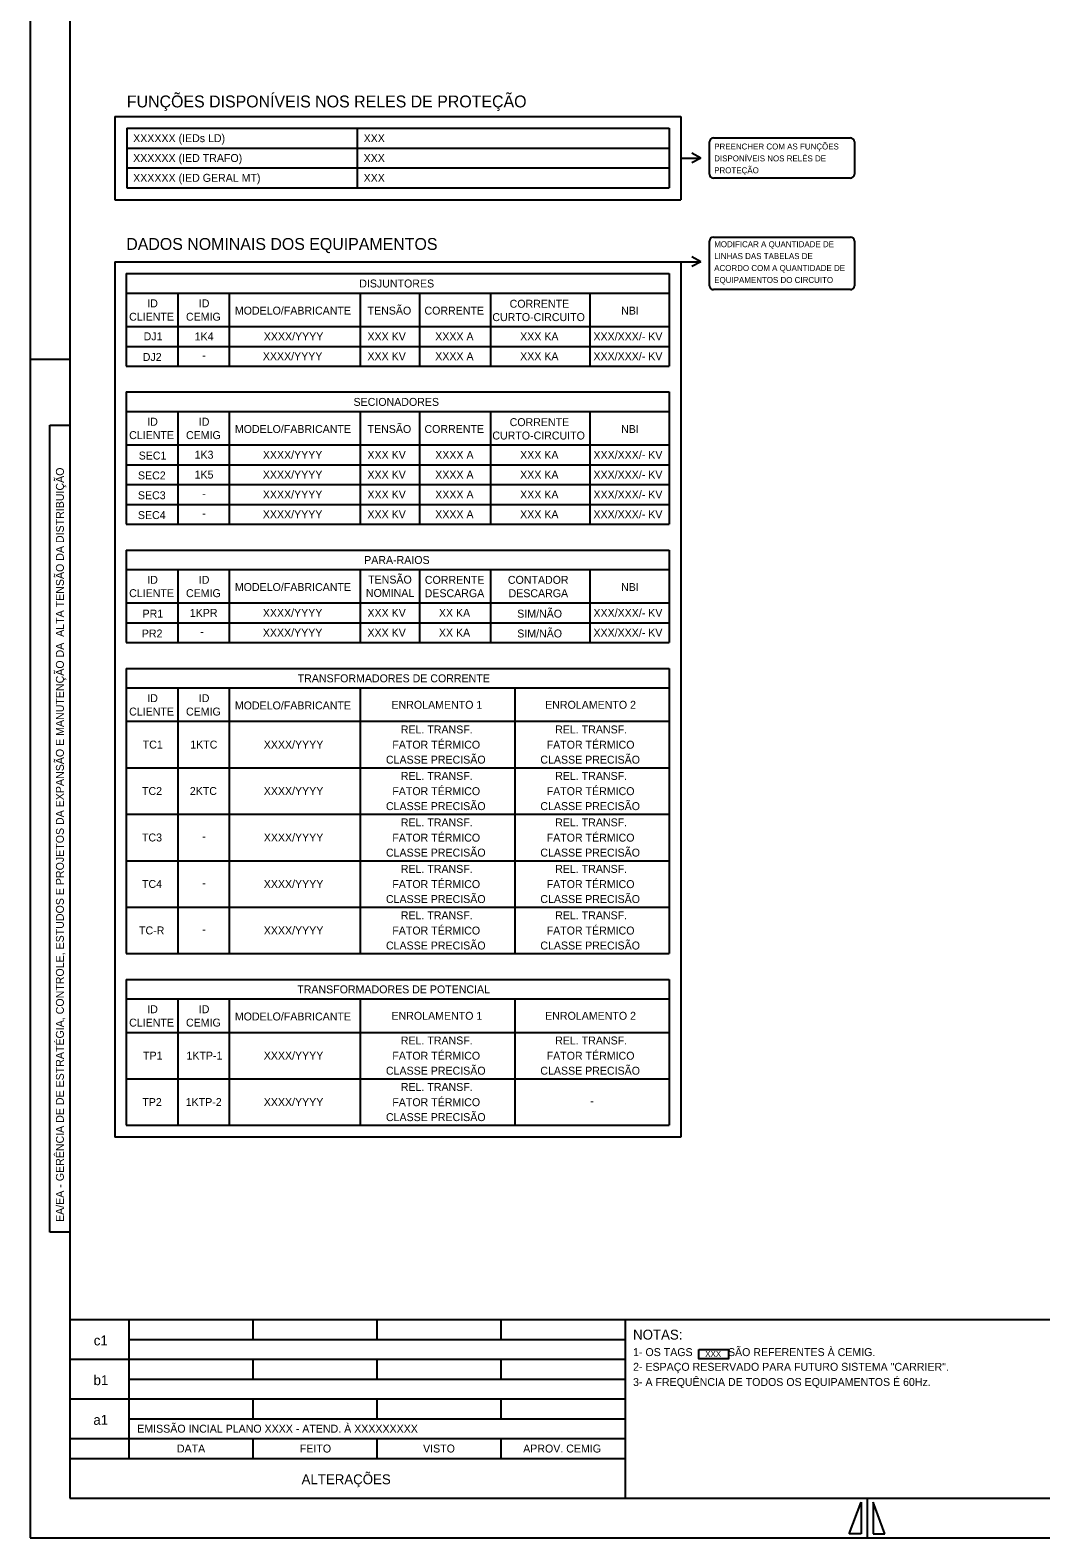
# Model space of a CAD drawing. Extents: x 563 to 1404, y 358 to 952.
# Drawn here: x 562.6 to 817.4, y 358 to 737.8 of the extents above; entities that cross this region are included whole.
import ezdxf

# ---------------------------------------------------------------- set-up
doc = ezdxf.new("R2010")
doc.units = 0
doc.layers.add('New Level (0)', color=7, linetype='Continuous')

# ---------------------------------------------------------------- blocks, each defined once
blk = doc.blocks.new('POINT_DISPLAY')
blk.add_line((0, 0), (0, 0))

msp = doc.modelspace()

# ---------------------------------------------------------------- linework, layer by layer
at = {"layer": 'New Level (0)'}
for p, q in [((562.58, 951.96), (562.58, 357.96)), ((562.58, 951.96), (562.58, 357.96)), ((572.58, 941.96), (572.58, 367.96)), ((572.58, 941.96), (572.58, 367.96)), ((583.96, 716.12), (583.96, 695.12)), ((583.96, 716.12), (726.65, 716.12)), ((726.65, 716.12), (726.65, 695.12)), ((586.96, 713.12), (723.65, 713.12)), ((586.96, 713.12), (586.96, 698.12)), ((586.96, 713.12), (586.96, 713.12)), ((586.96, 713.12), (586.96, 713.12)), ((645.01, 713.12), (645.01, 698.12)), ((723.65, 713.12), (723.65, 698.12)), ((734.84, 710.67), (742.19, 710.67)), ((742.19, 710.67), (769.38, 710.67)), ((586.96, 708.12), (723.65, 708.12)), ((731.68, 705.62), (729.38, 706.83)), ((733.84, 701.56), (733.84, 709.67)), ((770.38, 709.67), (770.38, 701.56)), ((586.96, 703.12), (723.65, 703.12)), ((726.65, 705.62), (731.68, 705.62)), ((731.68, 705.62), (729.38, 704.41)), ((769.38, 700.56), (734.84, 700.56)), ((586.96, 698.12), (723.65, 698.12)), ((583.96, 695.12), (726.65, 695.12)), ((733.84, 673.45), (733.84, 684.7)), ((734.84, 685.7), (742.19, 685.7)), ((742.19, 685.7), (769.38, 685.7)), ((770.38, 684.7), (770.38, 673.45)), ((731.68, 679.5), (729.38, 680.71)), ((583.96, 679.5), (726.65, 679.5)), ((583.96, 679.5), (583.96, 458.91)), ((586.81, 676.5), (586.81, 653.17)), ((586.81, 676.5), (723.65, 676.5)), ((723.65, 676.5), (723.65, 653.17)), ((726.65, 679.5), (731.68, 679.5)), ((726.65, 679.5), (726.65, 458.91)), ((731.68, 679.5), (729.38, 678.29)), ((769.38, 672.45), (734.84, 672.45)), ((723.65, 671.5), (586.81, 671.5)), ((599.81, 671.5), (599.81, 653.17)), ((612.81, 653.17), (612.81, 671.5)), ((645.81, 671.5), (645.81, 653.17)), ((660.72, 671.5), (660.72, 653.17)), ((678.66, 671.5), (678.66, 653.17)), ((703.66, 671.5), (703.66, 653.17)), ((586.81, 663.17), (723.65, 663.17)), ((586.81, 658.17), (723.65, 658.17)), ((562.58, 654.96), (572.58, 654.96)), ((586.81, 653.17), (723.65, 653.17)), ((586.81, 653.17), (586.81, 653.17)), ((586.81, 646.67), (586.81, 613.34)), ((586.81, 646.67), (723.65, 646.67)), ((723.65, 646.67), (723.65, 613.34)), ((567.58, 638.29), (572.58, 638.29)), ((567.58, 434.97), (567.58, 638.29)), ((723.65, 641.67), (586.81, 641.67)), ((599.81, 641.67), (599.81, 613.34)), ((612.81, 613.34), (612.81, 641.67)), ((645.81, 641.67), (645.81, 613.34)), ((660.72, 641.67), (660.72, 613.34)), ((678.66, 641.67), (678.66, 613.34)), ((703.66, 641.67), (703.66, 613.34)), ((586.81, 633.34), (723.65, 633.34)), ((586.81, 628.34), (723.65, 628.34)), ((586.81, 623.34), (723.65, 623.34)), ((586.81, 618.34), (723.65, 618.34)), ((586.81, 613.34), (723.65, 613.34)), ((586.81, 606.84), (586.81, 583.52)), ((586.81, 606.84), (723.65, 606.84)), ((723.65, 606.84), (723.65, 583.52)), ((723.65, 601.84), (586.81, 601.84)), ((599.81, 601.84), (599.81, 583.52)), ((612.81, 583.52), (612.81, 601.84)), ((645.81, 601.84), (645.81, 583.52)), ((660.72, 601.84), (660.72, 583.52)), ((678.66, 601.84), (678.66, 583.52)), ((703.66, 601.84), (703.66, 583.52)), ((586.81, 593.52), (723.65, 593.52)), ((629.06, 593.52), (723.65, 593.52)), ((586.81, 588.52), (723.65, 588.52)), ((586.81, 583.52), (723.65, 583.52)), ((586.81, 577.02), (586.81, 505.15)), ((586.81, 577.02), (723.65, 577.02)), ((723.65, 577.02), (723.65, 505.15)), ((723.65, 572.02), (586.81, 572.02)), ((599.81, 572.02), (599.81, 505.15)), ((612.81, 505.15), (612.81, 572.02)), ((645.81, 572.02), (645.81, 505.15)), ((684.73, 572.02), (684.73, 505.15)), ((586.81, 563.69), (723.65, 563.69)), ((586.81, 551.98), (723.65, 551.98)), ((586.81, 540.27), (723.65, 540.27)), ((586.81, 528.57), (723.65, 528.57)), ((586.81, 516.86), (723.65, 516.86)), ((586.81, 505.15), (723.65, 505.15)), ((586.81, 498.65), (586.81, 461.91)), ((586.81, 498.65), (723.65, 498.65)), ((723.65, 498.65), (723.65, 461.91)), ((723.65, 493.65), (586.81, 493.65)), ((599.81, 493.65), (599.81, 461.91)), ((612.81, 461.91), (612.81, 493.65)), ((645.81, 493.65), (645.81, 461.91)), ((684.73, 493.65), (684.73, 461.91)), ((586.81, 485.32), (723.65, 485.32)), ((586.81, 473.61), (723.65, 473.61)), ((586.81, 461.91), (723.65, 461.91)), ((726.65, 458.91), (583.96, 458.91)), ((572.58, 434.97), (567.58, 434.97)), ((572.58, 412.96), (1393.58, 412.96)), ((587.58, 377.96), (587.58, 412.96)), ((618.83, 407.96), (618.83, 412.96)), ((650.08, 407.96), (650.08, 412.96)), ((681.33, 407.96), (681.33, 412.96)), ((712.58, 412.96), (712.58, 367.96)), ((587.58, 407.96), (712.58, 407.96)), ((572.58, 402.96), (712.58, 402.96)), ((618.83, 397.96), (618.83, 402.96)), ((650.08, 397.96), (650.08, 402.96)), ((681.33, 397.96), (681.33, 402.96)), ((587.58, 397.96), (712.58, 397.96)), ((572.58, 392.96), (712.58, 392.96)), ((618.83, 387.96), (618.83, 392.96)), ((650.08, 387.96), (650.08, 392.96)), ((681.33, 387.96), (681.33, 392.96)), ((587.58, 387.96), (712.58, 387.96)), ((572.58, 382.96), (712.58, 382.96)), ((618.83, 377.96), (618.83, 382.96)), ((650.08, 377.96), (650.08, 382.96)), ((681.33, 377.96), (681.33, 382.96)), ((572.58, 377.96), (712.58, 377.96)), ((572.58, 367.96), (1393.58, 367.96)), ((572.58, 367.96), (1393.58, 367.96)), ((769.08, 358.96), (772.08, 366.96)), ((772.08, 366.96), (772.08, 358.96)), ((773.58, 367.96), (773.58, 357.96)), ((775.08, 366.96), (775.08, 358.96)), ((778.08, 358.96), (775.08, 366.96)), ((562.58, 357.96), (1403.58, 357.96)), ((562.58, 357.96), (1403.58, 357.96)), ((772.08, 358.96), (769.08, 358.96)), ((775.08, 358.96), (778.08, 358.96))]:
    msp.add_line(p, q, dxfattribs=at)
msp.add_lwpolyline([(731.16, 405.44), (738.67, 405.44), (738.67, 403.1), (731.16, 403.1)], close=True, dxfattribs=at)
for centre, start, end in [((734.84, 709.67), 90, 180), ((769.38, 709.67), 0, 90), ((734.84, 701.56), 180, 270), ((769.38, 701.56), 270, 0), ((734.84, 684.7), 90, 180), ((769.38, 684.7), 0, 90), ((734.84, 673.45), 180, 270), ((769.38, 673.45), 270, 0)]:
    msp.add_arc(centre, 1, start, end, dxfattribs=at)

# ---------------------------------------------------------------- block references
for p in [(670.01, 713.12), (655.23, 663.17), (655.23, 563.69), (655.23, 485.32)]:
    msp.add_blockref('POINT_DISPLAY', p, dxfattribs=at)

# ---------------------------------------------------------------- texts
for s, height, p in [('FUNÇÕES DISPONÍVEIS NOS RELES DE PROTEÇÃO', 3, (586.96, 718.37)), ('XXXXXX (IEDs LD)', 2, (588.55, 709.62)), ('XXX', 2, (646.65, 709.62)), ('XXXXXX (IED TRAFO)', 2, (588.55, 704.62)), ('XXX', 2, (646.65, 704.62)), ('PREENCHER COM AS FUNÇÕES ', 1.5, (735.03, 707.77)), ('DISPONÍVEIS NOS RELÉS DE ', 1.5, (735.03, 704.77)), ('PROTEÇÃO', 1.5, (735.03, 701.77)), ('XXXXXX (IED GERAL MT)', 2, (588.55, 699.62)), ('XXX', 2, (646.65, 699.62)), ('DADOS NOMINAIS DOS EQUIPAMENTOS', 3, (586.81, 682.46)), ('MODIFICAR A QUANTIDADE DE ', 1.5, (735.03, 683.15)), ('LINHAS DAS TABELAS DE ', 1.5, (735.03, 680.15)), ('ACORDO COM A QUANTIDADE DE ', 1.5, (735.03, 677.15)), ('DISJUNTORES', 2, (645.55, 673)), ('EQUIPAMENTOS DO CIRCUITO', 1.5, (735.03, 674.15)), ('ID', 2, (592.1, 668)), ('ID', 2, (605.1, 668)), ('TENSÃO', 2, (647.65, 666.17)), ('CORRENTE', 2, (683.46, 667.9)), ('CLIENTE', 2, (587.54, 664.63)), ('CEMIG', 2, (601.87, 664.63)), ('MODELO/FABRICANTE', 2, (614.19, 666.17)), ('CORRENTE', 2, (661.99, 666.17)), ('CURTO-CIRCUITO', 2, (679.1, 664.53)), ('NBI', 2, (711.56, 666.17)), ('DJ1', 2, (591.19, 659.68)), ('1K4', 2, (604.05, 659.67)), ('XXXX/YYYY', 2, (621.48, 659.67)), ('XXX KV', 2, (647.62, 659.67)), ('XXXX A', 2, (664.7, 659.67)), ('XXX KA', 2, (686.11, 659.67)), ('XXX/XXX/- KV', 2, (704.59, 659.67)), ('DJ2', 2, (590.97, 654.49)), ('-', 2, (605.94, 654.95)), ('XXXX/YYYY', 2, (621.24, 654.67)), ('XXX KV', 2, (647.62, 654.67)), ('XXXX A', 2, (664.7, 654.67)), ('XXX KA', 2, (686.11, 654.67)), ('XXX/XXX/- KV', 2, (704.59, 654.67)), ('SECIONADORES', 2, (644.11, 643.17)), ('ID', 2, (592.1, 638.17)), ('ID', 2, (605.1, 638.17)), ('MODELO/FABRICANTE', 2, (614.19, 636.34)), ('TENSÃO', 2, (647.65, 636.34)), ('CORRENTE', 2, (661.99, 636.34)), ('CORRENTE', 2, (683.46, 638.07)), ('NBI', 2, (711.56, 636.34)), ('CLIENTE', 2, (587.54, 634.8)), ('CEMIG', 2, (601.87, 634.8)), ('CURTO-CIRCUITO', 2, (679.1, 634.7)), ('SEC1', 2, (589.94, 629.65)), ('1K3', 2, (604.04, 629.86)), ('XXXX/YYYY', 2, (621.24, 629.84)), ('XXX KV', 2, (647.62, 629.84)), ('XXXX A', 2, (664.7, 629.84)), ('XXX KA', 2, (686.11, 629.84)), ('XXX/XXX/- KV', 2, (704.59, 629.84)), ('1K5', 2, (604.04, 624.86)), ('XXXX/YYYY', 2, (621.24, 624.84)), ('XXX KV', 2, (647.62, 624.84)), ('XXXX A', 2, (664.7, 624.84)), ('XXX KA', 2, (686.11, 624.84)), ('XXX/XXX/- KV', 2, (704.59, 624.84)), ('SEC2', 2, (589.76, 624.65)), ('SEC3', 2, (589.75, 619.65)), ('-', 2, (605.94, 620.12)), ('XXXX/YYYY', 2, (621.24, 619.84)), ('XXX KV', 2, (647.62, 619.84)), ('XXXX A', 2, (664.7, 619.84)), ('XXX KA', 2, (686.11, 619.84)), ('XXX/XXX/- KV', 2, (704.59, 619.84)), ('SEC4', 2, (589.75, 614.65)), ('-', 2, (605.94, 615.12)), ('XXXX/YYYY', 2, (621.24, 614.84)), ('XXX KV', 2, (647.62, 614.84)), ('XXXX A', 2, (664.7, 614.84)), ('XXX KA', 2, (686.11, 614.84)), ('XXX/XXX/- KV', 2, (704.59, 614.84)), ('PARA-RAIOS', 2, (646.79, 603.34)), ('ID', 2, (592.1, 598.34)), ('ID', 2, (605.1, 598.34)), ('TENSÃO ', 2, (647.79, 598.4)), ('CORRENTE', 2, (662.09, 598.33)), ('CONTADOR', 2, (683.02, 598.33)), ('CLIENTE', 2, (587.54, 594.98)), ('CEMIG', 2, (601.87, 594.98)), ('MODELO/FABRICANTE', 2, (614.19, 596.52)), ('NOMINAL', 2, (647.23, 595.03)), ('DESCARGA', 2, (662.05, 594.96)), ('DESCARGA', 2, (683.19, 594.96)), ('NBI', 2, (711.56, 596.52)), ('PR1', 2, (590.92, 589.82)), ('1KPR', 2, (602.83, 590.01)), ('XXXX/YYYY', 2, (621.24, 590.02)), ('XXX KV', 2, (647.62, 590.02)), ('XX KA', 2, (665.63, 590.02)), ('SIM/NÃO', 2, (685.38, 589.82)), ('XXX/XXX/- KV', 2, (704.59, 590.02)), ('PR2', 2, (590.74, 584.82)), ('-', 2, (605.47, 585.29)), ('XXXX/YYYY', 2, (621.24, 585.02)), ('XXX KV', 2, (647.62, 585.02)), ('XX KA', 2, (665.63, 585.02)), ('SIM/NÃO', 2, (685.38, 584.82)), ('XXX/XXX/- KV', 2, (704.59, 585.02)), ('TRANSFORMADORES DE CORRENTE', 2, (630.03, 573.52)), ('ID', 2, (592.1, 568.52)), ('ID', 2, (605.1, 568.52)), ('CLIENTE', 2, (587.54, 565.15)), ('CEMIG', 2, (601.87, 565.15)), ('MODELO/FABRICANTE', 2, (614.19, 566.69)), ('ENROLAMENTO 1', 2, (653.68, 566.85)), ('ENROLAMENTO 2', 2, (692.42, 566.85)), ('REL. TRANSF.', 2, (656.03, 560.64)), ('REL. TRANSF.', 2, (694.95, 560.64)), ('TC1', 2, (590.96, 556.83)), ('1KTC', 2, (602.95, 556.83)), ('XXXX/YYYY', 2, (621.48, 556.83)), ('FATOR TÉRMICO', 2, (653.88, 556.8)), ('FATOR TÉRMICO', 2, (692.8, 556.8)), ('CLASSE PRECISÃO', 2, (652.28, 553.03)), ('CLASSE PRECISÃO', 2, (691.2, 553.03)), ('REL. TRANSF.', 2, (656.03, 548.93)), ('REL. TRANSF.', 2, (694.95, 548.93)), ('TC2', 2, (590.78, 545.13)), ('2KTC', 2, (602.84, 545.13)), ('XXXX/YYYY', 2, (621.48, 545.13)), ('FATOR TÉRMICO', 2, (653.88, 545.09)), ('FATOR TÉRMICO', 2, (692.8, 545.09)), ('CLASSE PRECISÃO', 2, (652.28, 541.32)), ('CLASSE PRECISÃO', 2, (691.2, 541.32)), ('FATOR TÉRMICO', 2, (653.88, 533.38)), ('REL. TRANSF.', 2, (656.03, 537.22)), ('FATOR TÉRMICO', 2, (692.8, 533.38)), ('REL. TRANSF.', 2, (694.95, 537.22)), ('TC3', 2, (590.77, 533.42)), ('-', 2, (605.94, 533.7)), ('XXXX/YYYY', 2, (621.48, 533.42)), ('CLASSE PRECISÃO', 2, (652.28, 529.61)), ('CLASSE PRECISÃO', 2, (691.2, 529.61)), ('REL. TRANSF.', 2, (656.03, 525.51)), ('REL. TRANSF.', 2, (694.95, 525.51)), ('TC4', 2, (590.78, 521.71)), ('-', 2, (605.94, 521.99)), ('XXXX/YYYY', 2, (621.48, 521.71)), ('CLASSE PRECISÃO', 2, (652.28, 517.91)), ('FATOR TÉRMICO', 2, (653.88, 521.67)), ('CLASSE PRECISÃO', 2, (691.2, 517.91)), ('FATOR TÉRMICO', 2, (692.8, 521.67)), ('REL. TRANSF.', 2, (656.03, 513.81)), ('REL. TRANSF.', 2, (694.95, 513.81)), ('TC-R', 2, (590.03, 510)), ('-', 2, (605.94, 510.28)), ('XXXX/YYYY', 2, (621.48, 510)), ('FATOR TÉRMICO', 2, (653.88, 509.97)), ('FATOR TÉRMICO', 2, (692.8, 509.97)), ('CLASSE PRECISÃO', 2, (652.28, 506.2)), ('CLASSE PRECISÃO', 2, (691.2, 506.2)), ('TRANSFORMADORES DE POTENCIAL', 2, (629.92, 495.15)), ('ID', 2, (592.1, 490.15)), ('ID', 2, (605.1, 490.15)), ('MODELO/FABRICANTE', 2, (614.19, 488.32)), ('ENROLAMENTO 1', 2, (653.68, 488.49)), ('ENROLAMENTO 2', 2, (692.42, 488.49)), ('CLIENTE', 2, (587.54, 486.78)), ('CEMIG', 2, (601.87, 486.78)), ('REL. TRANSF.', 2, (656.03, 482.27)), ('REL. TRANSF.', 2, (694.95, 482.27)), ('TP1', 2, (591.04, 478.46)), ('1KTP-1', 2, (601.99, 478.46)), ('XXXX/YYYY', 2, (621.48, 478.47)), ('FATOR TÉRMICO', 2, (653.88, 478.43)), ('FATOR TÉRMICO', 2, (692.8, 478.43)), ('CLASSE PRECISÃO', 2, (652.28, 474.66)), ('CLASSE PRECISÃO', 2, (691.2, 474.66)), ('REL. TRANSF.', 2, (656.03, 470.56)), ('TP2', 2, (590.86, 466.76)), ('1KTP-2', 2, (601.8, 466.76)), ('XXXX/YYYY', 2, (621.48, 466.76)), ('FATOR TÉRMICO', 2, (653.88, 466.72)), ('-', 2, (703.81, 467.04)), ('CLASSE PRECISÃO', 2, (652.28, 462.96)), ('XXX', 1.5, (732.77, 403.54))]:
    msp.add_text(s, height=height).set_placement(p)
msp.add_text('EA/EA - GERÊNCIA DE DE ESTRATÉGIA, CONTROLE, ESTUDOS E PROJETOS DA EXPANSÃO E MANUTENÇÃO DA  ALTA TENSÃO DA DISTRIBUIÇÃO', height=2, rotation=90, dxfattribs=at).set_placement((571.08, 437.56))
for s, height, p in [('NOTAS:', 2.5, (714.58, 407.91)), ('c1', 2.5, (578.62, 406.44)), ('1- OS TAGS            SÃO REFERENTES À CEMIG.', 2, (714.58, 403.75)), ('b1', 2.5, (578.57, 396.44)), ('2- ESPAÇO RESERVADO PARA FUTURO SISTEMA "CARRIER".', 2, (714.58, 400.05)), ('3- A FREQUÊNCIA DE TODOS OS EQUIPAMENTOS É 60Hz.', 2, (714.58, 396.22)), ('a1', 2.5, (578.52, 386.44)), ('EMISSÃO INCIAL PLANO XXXX - ATEND. À XXXXXXXXX', 2, (589.58, 384.46)), ('DATA', 2, (599.58, 379.46)), ('FEITO', 2, (630.58, 379.46)), ('VISTO', 2, (661.64, 379.46)), ('APROV. CEMIG', 2, (686.88, 379.46)), ('ALTERAÇÕES', 2.5, (631.01, 371.46))]:
    msp.add_text(s, height=height, dxfattribs=at).set_placement(p)

doc.saveas('drawing.dxf')
